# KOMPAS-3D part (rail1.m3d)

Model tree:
1. X Axis
2. Y Axis
3. Z Axis
4. Origin
     Wall Thickness 1 = 1; Wall Thickness 2 = 1; Distance 1 = 50; Distance 2 = 10

Referenced files in C:\Work\01 К О М П А С\Модели примеры\2009_04_For_Poland_AXAPACK\My sample\Box_sample\: Base plate.a3d
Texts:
  Rail of BP
  Steel DIN 17102
  Three Point Plane
  Plane at Angle
  Line and Point Plane
  Axis through Two Vertices
  Axis of Feature
  Axis of Conical Surface
  Axis through Edge
  Trim by Surface
  Trim by Sketch
  Feature with No History
  Intersection Axis of Two Planes
  Two Line Plane
  Line and Face Plane
  Bend by line
  Hole in sheet body
  Cut in sheet body
  Point in CM
  Linear Dimension from Line to Point
  Surface Finish Symbol
  Geometric Tolerance Symbol
  Leader #1
  Leader #2
  Leader #3
  Shape Deviations and Datum
  Node point number
  Mark of coordination axis
  Node point designation
  Mark/Reference designation with leader
  Mark/reference designation on line
  Mark/Reference designation without leader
